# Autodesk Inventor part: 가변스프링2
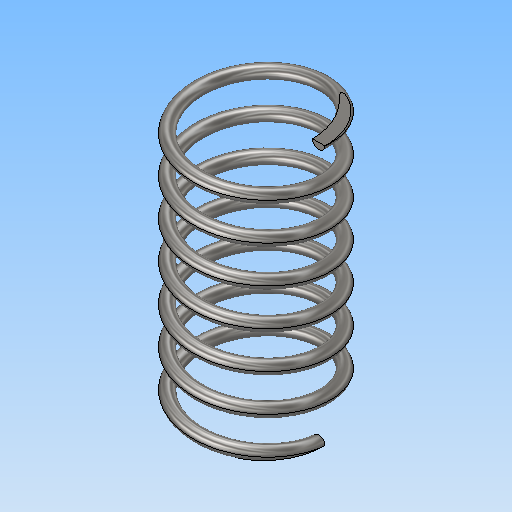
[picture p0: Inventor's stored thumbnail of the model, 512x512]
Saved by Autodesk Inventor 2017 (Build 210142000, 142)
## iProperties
Part Number: 가변스프링2
Material: 스테인레스 스틸
Document SubType Name: Modeling
Designer: MRC
Density: 8 g/cm^3
Appearance: 반연마
Mass: 10.9602 g
Surface Area: 27.6886 cm^2
Volume: 1.37003 cm^3
Author: MRC
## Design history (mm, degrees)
sketch "스케치1"
  geometry: L1 (0, 0)-(10, 0); L2 (10, 0)-(10, 41.411); L3 (10, 41.411)-(0, 41.411); L4 (0, 41.411)-(0, 0); C1 r 1 at (10, 0)
  constraints: 8 end point, 2 parallel, 1 centre point, 1 coincident, 1 horizontal, 1 perpendicular
  dimensions: "d1" = 41.4112 distance of L3.end L1.start (derived); "d2" = 20 diameter of L2 L4; "d3" = 2 diameter of C1
feature "코일1" sketch "스케치1" pitch "d4" = 10; turns "d6" = 7; dims "d5" = 41.4112 (= d1), "d7" = 0, angle "d8" = 90 deg, angle "d9" = 90 deg, "d10" = 0, "d11" = 0
sketch "스케치2"
  geometry: L1 (-20, 41.411)-(20, 41.411); L2 (20, 41.411)-(20, 0); L3 (20, 0)-(-20, 0); L4 (-20, 0)-(-20, 41.411); L5 (0, 41.411)-(0, 0) reference; 2 further points
  constraints: 8 end point, 2 midpoint, 2 parallel, 1 coincident, 1 horizontal, 1 perpendicular
  dimensions: "d12" = 40 distance between parallel lines of L4 L2
extrude "돌출1" sketch "스케치2" stored distance "d13" = 0; taper "d14" = 0 deg
node "솔리드1"
